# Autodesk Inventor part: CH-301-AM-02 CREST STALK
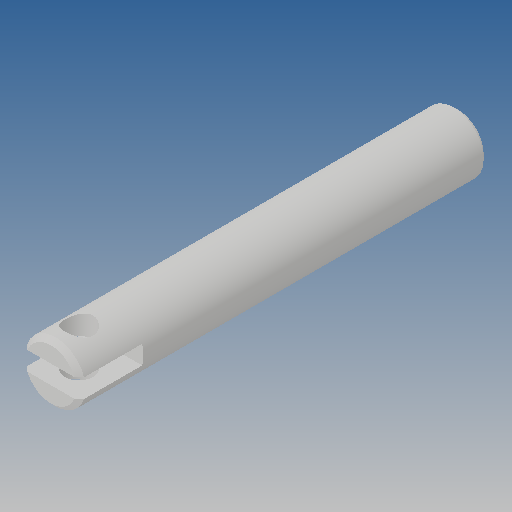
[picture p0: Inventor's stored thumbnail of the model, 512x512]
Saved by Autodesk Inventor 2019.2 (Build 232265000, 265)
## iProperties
Created: 2012-09
Part Number: CH-301-AM-02 CREST STALK
Material: Ogólny
Document SubType Name: Modeling
Designer: CADENGINEERING4
Density: 1 g/cm^3
Appearance: Domyślna
Author: CADENGINEERING4
Revision Number: ÈÎºÎ
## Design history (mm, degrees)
feature "µ¹½Ç2"
node "Bryła1"
